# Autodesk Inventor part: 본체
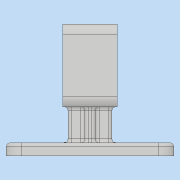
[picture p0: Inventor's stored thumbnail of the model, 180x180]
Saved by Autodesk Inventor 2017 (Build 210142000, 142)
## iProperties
Part Number: 본체
Material: 일반
Document SubType Name: Modeling
Designer: 222
Density: 1 g/cm^3
Appearance: 기본값
Author: 222
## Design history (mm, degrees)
sketch "스케치1"
  geometry: L1 (65, 49)-(-65, 49); L2 (-65, 49)-(-65, -49); L3 (-65, -49)-(65, -49); L4 (65, -49)-(65, 49); L5 (65, 49)-(-65, -49); L6 (-65, 49)-(65, -49); 1 further point
  constraints: 12 end point, 2 midpoint, 2 parallel, 1 horizontal, 1 perpendicular
  dimensions: "d0" = 130 distance of L3.end L2.end; "d1" = 98 distance of L2.end L1.end
extrude "돌출1" new body sketch "스케치1" distance "d2" = 10; taper "d3" = 0 deg
sketch "스케치2"
  geometry: 1 further point
node "작업 평면1"
sketch "스케치3"
  geometry: L1 (30, 38)-(94, 38); L2 (94, 38)-(94, 102); L3 (94, 102)-(30, 102); L4 (30, 102)-(30, 38); L5 (30, 38)-(94, 102); L6 (94, 38)-(30, 102); L7 (0, 0)-(98, 0) reference; L8 (98, 10)-(0, 10) reference; L9 (98, 0)-(98, 10) reference; 4 further points
  constraints: 12 end point, 3 midpoint, 2 parallel, 1 horizontal, 1 perpendicular, 1 point on line, 1 vertical alignment
  dimensions: "d5" = 64 distance of L2.end L3.end; "d6" = 64 distance of L1.end L2.end; "d7" = 70 distance from line of L7 point (62, 70); "d8" = 36 distance from line of L9 point (62, 10)
extrude "돌출2" join sketch "스케치3" distance "d9" = 42; taper "d10" = 0 deg
sketch "스케치4"
  geometry: L1 (-17, -9)-(-17, -17); L2 (-17, -17)-(-4, -17); L3 (-4, -17)-(-4, -33); L4 (-4, -33)-(4, -33); L5 (4, -33)-(4, -17); L6 (4, -17)-(17, -17); L7 (17, -17)-(17, -9); L8 (17, -9)-(4, -9); L9 (4, -9)-(4, 7); L10 (4, 7)-(-4, 7); L11 (-4, 7)-(-4, -9); L12 (-17, -9)-(-4, -9); L13 (65, 49)-(-65, 49) reference; 10 further points
  constraints: 24 end point, 9 midpoint, 8 perpendicular, 7 point on line, 3 vertical alignment, 2 horizontal alignment, 1 vertical
  dimensions: "d11" = 8 distance of L6.end L7.end; "d12" = 8 distance of L9.end L10.end; "d13" = 66 distance from line of L6.end L13; "d15" = 34 distance between parallel lines of L7 L1; "d16" = 17 distance from line of point (0, 0) L1; "d17" = 40 distance between parallel lines of L4 L10; "d18" = 42 distance between parallel lines of L13 L10
extrude "돌출3" join sketch "스케치4" stored distance "d19" = 42; taper "d20" = 0 deg
sketch "스케치5"
  geometry: L1 (66, 10)-(58, 10) reference; L2 (0, 0)-(98, 0) reference; C1 r 21 at (62, 70); 2 further points
  constraints: 1 centre point, 1 midpoint, 1 vertical alignment
  dimensions: "d21" = 42 diameter of C1; "d22" = 70 distance from line of L2 C1.centre
extrude "돌출4" cut sketch "스케치5" distance "d23" = 15; taper "d24" = 0 deg
sketch "스케치6"
  geometry: C1 r 21 at (0, 0) reference; C2 r 18 at (0, 0); 1 further point
  constraints: 1 centre point, 1 coincident
  dimensions: "d25" = 36 diameter of C2
extrude "돌출5" cut sketch "스케치6" distance "d26" = 6; taper "d27" = 0 deg
sketch "스케치7"
  geometry: L1 (-98, 0)-(0, 0) reference; L2 (-58, 10)-(-66, 10) reference; C1 r 21 at (-62, 70); 2 further points
  constraints: 1 centre point, 1 midpoint, 1 vertical alignment
  dimensions: "d28" = 42 diameter of C1; "d29" = 70 distance from line of C1.centre L1
extrude "돌출6" cut sketch "스케치7" distance "d30" = 15; taper "d31" = 0 deg
sketch "스케치8"
  geometry: C1 r 21 at (0, 0) reference; C2 r 18 at (0, 0); 1 further point
  constraints: 1 centre point, 1 coincident
  dimensions: "d32" = 36 diameter of C2
extrude "돌출7" cut sketch "스케치8" distance "d33" = 6; taper "d34" = 0 deg
sketch "스케치9"
  geometry: C1 r 21 at (62, 70) reference; 2 further points
  dimensions: "d35" = 24 horizontal distance of C1.centre point (38, 94); "d36" = 24 horizontal distance of C1.centre point (38, 94)
hole "구멍1" sketch "스케치9" at (38, 94) diameter "d37" = 3.242; stored, may be unused: countersink angle "d41" = 90 deg, drill point angle "d43" = 118 deg; dims "d38" = 8, "d39" = 4, "d40" = 2, "d42" = 10
sketch "스케치10"
  geometry: L1 (65, 49)-(-65, 49) reference; L2 (-65, 49)-(-65, -49) reference; C1 r 4.5 at (-53, 37); 1 further point
  constraints: 1 centre point
  dimensions: "d50" = 9 diameter of C1; "d51" = 12 distance from line of L1 C1.centre; "d52" = 12 distance from line of L2 C1.centre
extrude "돌출8" cut sketch "스케치10" stored distance "d53" = 6; taper "d54" = 0 deg
fillet "모깎기1" dims "d61" = 3
fillet "모깎기2" dims "d62" = 12
fillet "모깎기3" dims "d63" = 8
fillet "모깎기4" dims "d64" = 3
fillet "모깎기5" dims "d65" = 3
chamfer "모따기1" distance "d66" = 1; stored, may be unused: second distance "d67" = 2, angle "d68" = 45 deg
fillet "모깎기6" dims "d69" = 0.3
sketch "스케치11"
  geometry: L1 (53, 49)-(-53, 49) reference; L2 (65, -37)-(65, 37) reference; 2 further points
  constraints: 1 other
  dimensions: "d70" = 10 distance from line of L1 point (0, 39); "d71" = 65 distance from line of L2 point (0, 39)
feature "엠보싱1" sketch "스케치11" dims "d0" = 130, "d1" = 98, "d5" = 64, "d6" = 64, "d7" = 70, "d8" = 36, "d72" = 0.5, "d73" = 0
node "솔리드1"
pattern_linear "직사각형 패턴1" dims "d46" = -48, "d49" = -48
mirror "미러1"
pattern_linear "직사각형 패턴2" dims "d57" = -106, "d60" = -74
other parameters: "d4" = -44
